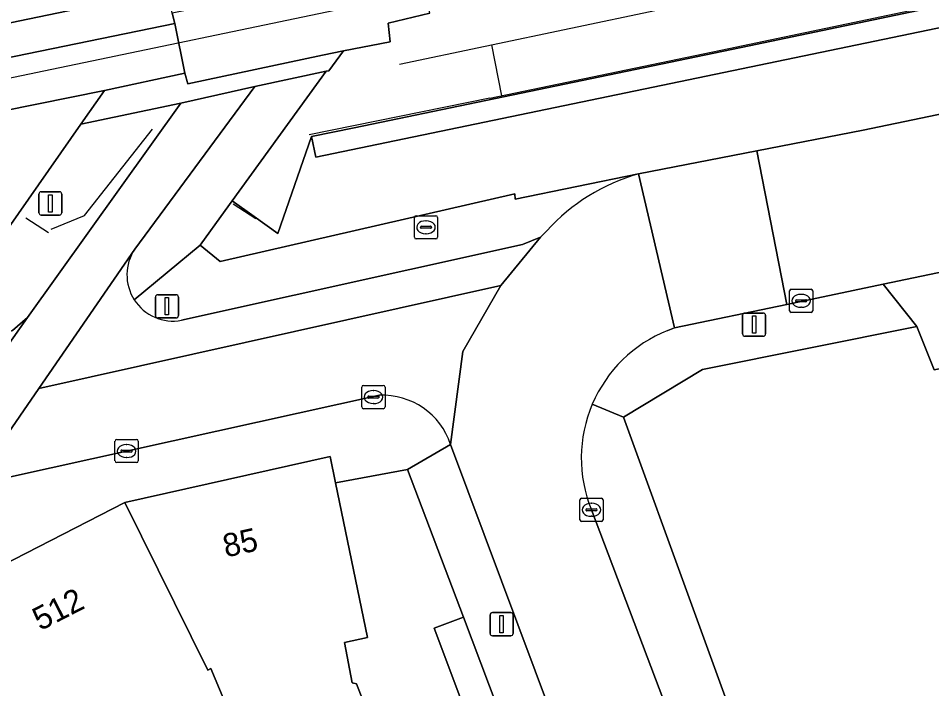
# Model space of a CAD drawing. Extents: x 162989 to 165008, y 383432 to 384338.
# Drawn here: x 163879.92 to 163919.28, y 384116.68 to 384145.59 of the extents above; entities that cross this region are included whole.
import ezdxf

# ---------------------------------------------------------------- set-up
doc = ezdxf.new("R2010")
doc.units = 0
for name, color, linetype in [('IMGEO_Erf', 7, 'Continuous'), ('IMGEO_Fietspad_open', 7, 'Continuous'), ('IMGEO_Geluidsscherm', 7, 'Continuous'), ('IMGEO_Groenvoorziening', 7, 'Continuous'), ('IMGEO_Haag', 7, 'Continuous'), ('IMGEO_Hek', 7, 'Continuous'), ('IMGEO_Kolk', 7, 'Continuous'), ('IMGEO_Lichtmast', 7, 'Continuous'), ('IMGEO_Overweg_gesloten', 7, 'Continuous'), ('IMGEO_Pand', 7, 'Continuous'), ('IMGEO_Pand_nummerreeks', 7, 'Continuous'), ('IMGEO_Rijbaan_lokaal_gesloten', 7, 'Continuous'), ('IMGEO_Rijbaan_lokaal_open', 7, 'Continuous'), ('IMGEO_Rioolput', 7, 'Continuous'), ('IMGEO_Spoor', 7, 'Continuous'), ('IMGEO_Spoorbaan_halfverhard', 7, 'Continuous'), ('IMGEO_Terreindeel_open', 7, 'Continuous'), ('IMGEO_Verkeerseiland_open', 7, 'Continuous'), ('IMGEO_Verkeersregelinstallatiepaal', 7, 'Continuous'), ('IMGEO_Voetpad_open', 7, 'Continuous')]:
    doc.layers.add(name, color=color, linetype=linetype)

msp = doc.modelspace()

# ---------------------------------------------------------------- linework, layer by layer
at = {"layer": 'IMGEO_Erf'}
msp.add_lwpolyline([(163944.693, 384087.722), (163943.187, 384090.664), (163940.668, 384096.069), (163940.042, 384097.411), (163938.387, 384100.469), (163933.086, 384111.619), (163931.815, 384114.219), (163930.51, 384116.89), (163930.356, 384117.204), (163925.265, 384126.849), (163923.141, 384131.213), (163919.387, 384130.435), (163918.639, 384132.305), (163909.406, 384130.442), (163905.997, 384128.384), (163911.891, 384112.19), (163917.32, 384097.768), (163932.033, 384058.943), (163947.096, 384019.256)], dxfattribs=at)
msp.add_lwpolyline([(163896.692, 384126.141), (163893.588, 384125.567), (163894.973, 384118.889), (163893.974, 384118.682), (163894.306, 384116.933), (163894.496, 384116.901), (163895.601, 384114.038), (163899.299, 384115.433), (163897.84, 384119.301), (163899.1, 384119.776)], close=True, dxfattribs=at)
at = {"layer": 'IMGEO_Fietspad_open'}
for points in [[(163858.262, 384092.719), (163870.014, 384113.204), (163876.697, 384123.662), (163880.797, 384129.62), (163884.94, 384135.639), (163890.116, 384142.65), (163886.926, 384141.93), (163880.31, 384132.681), (163877.756, 384129.074), (163877.678, 384128.954), (163873.799, 384123.243), (163873.714, 384123.118), (163868.266, 384114.374), (163867.368, 384112.852)], [(163900.713, 384134.073), (163902.42, 384136.156), (163901.655, 384135.828), (163886.954, 384132.566)], [(163884.94, 384135.639), (163880.797, 384129.62), (163900.713, 384134.073)], [(163877.756, 384129.074), (163880.31, 384132.681), (163879.674, 384132.131), (163878.95, 384131.916), (163877.192, 384131.789)]]:
    msp.add_lwpolyline(points, dxfattribs=at)
for centre, radius, start, end in [((163886.591, 384134.527), 1.991, 146.0445, 212.645), ((163886.595, 384134.527), 1.994, 212.5967, 280.3836)]:
    msp.add_arc(centre, radius, start, end, dxfattribs=at)
at = {"layer": 'IMGEO_Geluidsscherm'}
for points in [[(163900.238, 384142.138), (163910.539, 384144.282), (163924.865, 384147.3), (163937.597, 384149.952), (163949.238, 384152.367)], [(163900.238, 384142.138), (163892.449, 384140.554)]]:
    msp.add_lwpolyline(points, dxfattribs=at)
at = {"layer": 'IMGEO_Groenvoorziening'}
for points in [[(163976.433, 384156.982), (163892.745, 384139.603), (163892.562, 384140.484), (163891.111, 384136.301), (163890.081, 384137.041), (163889.139, 384137.718), (163888.832, 384137.295), (163887.752, 384135.808), (163888.618, 384135.1), (163901.317, 384138.016), (163901.331, 384137.791), (163906.646, 384138.881), (163911.749, 384139.874), (163916.336, 384140.767), (163989.771, 384156.06)], [(163953.785, 384153.248), (163943.293, 384151.084), (163911.419, 384144.396), (163894.397, 384140.865), (163892.562, 384140.484), (163892.745, 384139.603), (163976.433, 384156.982)]]:
    msp.add_lwpolyline(points, dxfattribs=at)
at = {"layer": 'IMGEO_Haag'}
msp.add_lwpolyline([(163953.785, 384153.248), (163943.293, 384151.084), (163911.419, 384144.396), (163894.397, 384140.865), (163892.562, 384140.484), (163892.745, 384139.603), (163976.433, 384156.982)], dxfattribs=at)
at = {"layer": 'IMGEO_Hek'}
for points in [[(163896.346, 384143.612), (163907.423, 384145.929), (163917.143, 384147.909)], [(163900.306, 384144.44), (163900.741, 384142.243)], [(163881.334, 384136.493), (163882.776, 384137.081), (163885.697, 384140.808)], [(163892.562, 384140.484), (163891.111, 384136.301), (163890.081, 384137.041), (163889.139, 384137.718)], [(163889.181, 384137.585), (163890.162, 384136.954)], [(163880.249, 384136.986), (163881.223, 384136.354)]]:
    msp.add_lwpolyline(points, dxfattribs=at)
at = {"layer": 'IMGEO_Kolk'}
for p, q in [((163913.158, 384132.98), (163913.158, 384133.832)), ((163913.233, 384133.906), (163914.085, 384133.906)), ((163914.159, 384133.832), (163914.159, 384132.98)), ((163913.417, 384133.4), (163913.417, 384133.412)), ((163913.855, 384133.363), (163913.457, 384133.363)), ((163913.46, 384133.449), (163913.858, 384133.449)), ((163913.646, 384133.686), (163913.671, 384133.686)), ((163913.901, 384133.412), (163913.901, 384133.4)), ((163913.669, 384133.126), (163913.644, 384133.126)), ((163914.085, 384132.906), (163913.233, 384132.906)), ((163894.722, 384128.831), (163894.722, 384129.683)), ((163894.797, 384129.757), (163895.649, 384129.757)), ((163895.21, 384129.537), (163895.235, 384129.537)), ((163895.723, 384129.683), (163895.723, 384128.831)), ((163894.981, 384129.251), (163894.981, 384129.263)), ((163895.419, 384129.214), (163895.021, 384129.214)), ((163895.024, 384129.3), (163895.422, 384129.3)), ((163895.233, 384128.977), (163895.208, 384128.977)), ((163895.465, 384129.263), (163895.465, 384129.251)), ((163895.649, 384128.757), (163894.797, 384128.757)), ((163884.161, 384127.43), (163885.013, 384127.43)), ((163884.086, 384126.504), (163884.086, 384127.356)), ((163884.574, 384127.21), (163884.599, 384127.21)), ((163885.087, 384127.356), (163885.087, 384126.504)), ((163884.345, 384126.924), (163884.345, 384126.936)), ((163884.783, 384126.887), (163884.385, 384126.887)), ((163884.388, 384126.973), (163884.786, 384126.973)), ((163884.597, 384126.65), (163884.572, 384126.65)), ((163884.829, 384126.936), (163884.829, 384126.924)), ((163885.013, 384126.43), (163884.161, 384126.43)), ((163904.119, 384123.971), (163904.119, 384124.823)), ((163904.194, 384124.897), (163905.046, 384124.897)), ((163904.607, 384124.677), (163904.632, 384124.677)), ((163905.12, 384124.823), (163905.12, 384123.971)), ((163904.378, 384124.391), (163904.378, 384124.403)), ((163904.816, 384124.354), (163904.418, 384124.354)), ((163904.421, 384124.44), (163904.819, 384124.44)), ((163904.862, 384124.403), (163904.862, 384124.391)), ((163905.046, 384123.897), (163904.194, 384123.897)), ((163904.63, 384124.117), (163904.605, 384124.117))]:
    msp.add_line(p, q, dxfattribs=at)
for points in [[(163913.158, 384132.98), (163913.158, 384133.832)], [(163913.233, 384133.906), (163914.085, 384133.906)], [(163914.159, 384133.832), (163914.159, 384132.98)], [(163914.085, 384132.906), (163913.233, 384132.906)], [(163894.722, 384128.831), (163894.722, 384129.683)], [(163894.797, 384129.757), (163895.649, 384129.757)], [(163895.723, 384129.683), (163895.723, 384128.831)], [(163895.649, 384128.757), (163894.797, 384128.757)], [(163884.161, 384127.43), (163885.013, 384127.43)], [(163884.086, 384126.504), (163884.086, 384127.356)], [(163885.087, 384127.356), (163885.087, 384126.504)], [(163885.013, 384126.43), (163884.161, 384126.43)], [(163904.119, 384123.971), (163904.119, 384124.823)], [(163904.194, 384124.897), (163905.046, 384124.897)], [(163905.12, 384124.823), (163905.12, 384123.971)], [(163905.046, 384123.897), (163904.194, 384123.897)]]:
    msp.add_lwpolyline(points, dxfattribs=at)
for centre, radius, start, end in [((163913.235, 384133.83), 0.0765, 91.552, 178.448), ((163913.235, 384133.83), 0.0765, 91.552, 178.448), ((163914.083, 384133.83), 0.0765, 1.552, 88.448), ((163914.083, 384133.83), 0.0765, 1.552, 88.448), ((163913.457, 384133.409), 0.0403, 85.8775, 175.7526), ((163913.454, 384133.399), 0.0366, 178.938, 274.7102), ((163913.858, 384133.406), 0.043, 264.8664, 352.4533), ((163913.862, 384133.411), 0.0386, 1.7309, 96.639), ((163913.235, 384132.982), 0.0765, 181.552, 268.448), ((163913.235, 384132.982), 0.0765, 181.552, 268.448), ((163914.083, 384132.982), 0.0765, 271.552, 358.448), ((163914.083, 384132.982), 0.0765, 271.552, 358.448), ((163894.799, 384129.681), 0.0765, 91.552, 178.448), ((163894.799, 384129.681), 0.0765, 91.552, 178.448), ((163895.647, 384129.681), 0.0765, 1.552, 88.448), ((163895.647, 384129.681), 0.0765, 1.552, 88.448), ((163895.021, 384129.26), 0.0403, 85.8775, 175.7526), ((163895.018, 384129.25), 0.0366, 178.938, 274.7102), ((163895.422, 384129.257), 0.043, 264.8664, 352.4533), ((163895.426, 384129.262), 0.0386, 1.7309, 96.639), ((163894.799, 384128.833), 0.0765, 181.552, 268.448), ((163894.799, 384128.833), 0.0765, 181.552, 268.448), ((163895.647, 384128.833), 0.0765, 271.552, 358.448), ((163895.647, 384128.833), 0.0765, 271.552, 358.448), ((163884.163, 384127.354), 0.0765, 91.552, 178.448), ((163884.163, 384127.354), 0.0765, 91.552, 178.448), ((163885.011, 384127.354), 0.0765, 1.552, 88.448), ((163885.011, 384127.354), 0.0765, 1.552, 88.448), ((163884.385, 384126.933), 0.0403, 85.8775, 175.7526), ((163884.382, 384126.923), 0.0366, 178.938, 274.7102), ((163884.786, 384126.93), 0.043, 264.8664, 352.4533), ((163884.79, 384126.935), 0.0386, 1.7309, 96.639), ((163884.163, 384126.506), 0.0765, 181.552, 268.448), ((163884.163, 384126.506), 0.0765, 181.552, 268.448), ((163885.011, 384126.506), 0.0765, 271.552, 358.448), ((163885.011, 384126.506), 0.0765, 271.552, 358.448), ((163904.196, 384124.821), 0.0765, 91.552, 178.448), ((163904.196, 384124.821), 0.0765, 91.552, 178.448), ((163905.044, 384124.821), 0.0765, 1.552, 88.448), ((163905.044, 384124.821), 0.0765, 1.552, 88.448), ((163904.418, 384124.4), 0.0403, 85.8775, 175.7526), ((163904.415, 384124.39), 0.0366, 178.938, 274.7102), ((163904.819, 384124.397), 0.043, 264.8664, 352.4533), ((163904.823, 384124.402), 0.0386, 1.7309, 96.639), ((163904.196, 384123.973), 0.0765, 181.552, 268.448), ((163904.196, 384123.973), 0.0765, 181.552, 268.448), ((163905.044, 384123.973), 0.0765, 271.552, 358.448), ((163905.044, 384123.973), 0.0765, 271.552, 358.448)]:
    msp.add_arc(centre, radius, start, end, dxfattribs=at)
for centre, major_axis, ratio, start_param, end_param in [((163913.645, 384133.406), (-0.387, 0.002), 0.722429, 4.712389, 7.853982), ((163913.67, 384133.406), (-0.39, 0.002), 0.717154, 1.570796, 4.712389), ((163895.209, 384129.257), (-0.387, 0.002), 0.722429, 4.712389, 7.853982), ((163895.234, 384129.257), (-0.39, 0.002), 0.717154, 1.570796, 4.712389), ((163884.573, 384126.93), (-0.387, 0.002), 0.722429, 4.712389, 7.853982), ((163884.598, 384126.93), (-0.39, 0.002), 0.717154, 1.570796, 4.712389), ((163904.606, 384124.397), (-0.387, 0.002), 0.722429, 4.712389, 7.853982), ((163904.631, 384124.397), (-0.39, 0.002), 0.717154, 1.570796, 4.712389)]:
    msp.add_ellipse(centre, major_axis=major_axis, ratio=ratio, start_param=start_param, end_param=end_param, dxfattribs=at)
at = {"layer": 'IMGEO_Lichtmast'}
for p, q in [((163911.136, 384131.981), (163911.136, 384132.781)), ((163911.136, 384132.781), (163911.136, 384131.981)), ((163911.236, 384132.881), (163912.026, 384132.881)), ((163912.026, 384132.881), (163911.236, 384132.881)), ((163912.126, 384132.781), (163912.126, 384131.981)), ((163912.126, 384131.981), (163912.126, 384132.781)), ((163912.026, 384131.881), (163911.236, 384131.881)), ((163911.236, 384131.881), (163912.026, 384131.881)), ((163900.35, 384119.965), (163901.14, 384119.965)), ((163901.14, 384119.965), (163900.35, 384119.965)), ((163900.25, 384119.065), (163900.25, 384119.865)), ((163900.25, 384119.865), (163900.25, 384119.065)), ((163901.24, 384119.865), (163901.24, 384119.065)), ((163901.24, 384119.065), (163901.24, 384119.865)), ((163901.14, 384118.965), (163900.35, 384118.965)), ((163900.35, 384118.965), (163901.14, 384118.965))]:
    msp.add_line(p, q, dxfattribs=at)
for points in [[(163911.556, 384132.756), (163911.706, 384132.756), (163911.706, 384132.006), (163911.556, 384132.006), (163911.556, 384132.756)], [(163900.67, 384119.84), (163900.82, 384119.84), (163900.82, 384119.09), (163900.67, 384119.09), (163900.67, 384119.84)]]:
    msp.add_lwpolyline(points, dxfattribs=at)
for centre, start, end in [((163911.236, 384132.781), 90, 180), ((163911.236, 384132.781), 90, 180), ((163912.026, 384132.781), 0, 90), ((163912.026, 384132.781), 360, 90), ((163911.236, 384131.981), 180, 270), ((163911.236, 384131.981), 180, 270), ((163912.026, 384131.981), 270, 0), ((163912.026, 384131.981), 270, 0), ((163900.35, 384119.865), 90, 180), ((163900.35, 384119.865), 90, 180), ((163901.14, 384119.865), 0, 90), ((163901.14, 384119.865), 360, 90), ((163900.35, 384119.065), 180, 270), ((163900.35, 384119.065), 180, 270), ((163901.14, 384119.065), 270, 0), ((163901.14, 384119.065), 270, 0)]:
    msp.add_arc(centre, 0.1, start, end, dxfattribs=at)
at = {"layer": 'IMGEO_Overweg_gesloten'}
for points in [[(163887.436, 384147.028), (163890.186, 384147.601), (163889.762, 384149.774), (163888.918, 384149.602), (163880.117, 384147.805), (163875.498, 384146.807), (163872.137, 384146.081), (163872.55, 384143.931), (163887.405, 384147.022)], [(163890.332, 384146.853), (163890.383, 384146.595), (163886.557, 384145.81), (163886.663, 384145.362), (163887.095, 384143.225), (163887.222, 384142.762), (163893.034, 384143.99), (163893.927, 384144.186), (163895.946, 384144.574), (163895.864, 384145.378), (163897.66, 384145.8), (163897.335, 384147.214), (163899.364, 384147.663), (163899.232, 384148.352), (163899.175, 384148.649)], [(163887.095, 384143.225), (163886.663, 384145.362), (163875.53, 384143.078), (163872.569, 384142.426), (163872.034, 384142.315), (163869.07, 384141.702), (163869.535, 384139.534), (163870.466, 384139.819), (163883.633, 384142.477)]]:
    msp.add_lwpolyline(points, close=True, dxfattribs=at)
at = {"layer": 'IMGEO_Pand'}
for points in [[(163895.601, 384114.038), (163894.496, 384116.901), (163894.306, 384116.933), (163893.974, 384118.682), (163894.973, 384118.889), (163893.588, 384125.567), (163893.354, 384126.698), (163884.516, 384124.719), (163888.09, 384117.489), (163888.221, 384117.556), (163889.151, 384115.323)], [(163901.721, 384112.825), (163899.1, 384119.776), (163897.84, 384119.301), (163899.299, 384115.433)]]:
    msp.add_lwpolyline(points, dxfattribs=at)
msp.add_lwpolyline([(163884.516, 384124.719), (163876.517, 384120.624), (163878.774, 384116.163), (163880.994, 384111.502), (163881.419, 384111.589), (163883.158, 384112.529), (163884.344, 384113.17), (163884.496, 384112.879), (163889.151, 384115.323), (163888.221, 384117.556), (163888.09, 384117.489)], close=True, dxfattribs=at)
at = {"layer": 'IMGEO_Rijbaan_lokaal_gesloten'}
for points in [[(163923.113, 384135.366), (163960.826, 384143.251), (163966.926, 384144.526), (163982.743, 384147.834), (163986.464, 384148.612), (163997.553, 384150.93), (164000, 384151.442), (164001.293, 384151.706), (164009.768, 384153.438), (164008.393, 384160.13), (164000, 384158.405), (163989.771, 384156.06), (163916.336, 384140.767), (163911.749, 384139.874), (163913.038, 384133.253), (163917.195, 384134.125)], [(163886.663, 384145.362), (163886.557, 384145.81), (163886.498, 384146.061), (163887.007, 384146.153), (163887.47, 384146.785), (163887.436, 384147.028), (163887.405, 384147.022), (163872.55, 384143.931), (163872.638, 384143.474), (163872.682, 384143.27), (163872.009, 384142.45), (163872.034, 384142.315), (163872.569, 384142.426), (163875.53, 384143.078)]]:
    msp.add_lwpolyline(points, close=True, dxfattribs=at)
msp.add_lwpolyline([(163876.691, 384132.556), (163882.616, 384141.024), (163883.633, 384142.477), (163870.466, 384139.819)], dxfattribs=at)
at = {"layer": 'IMGEO_Rijbaan_lokaal_open'}
msp.add_lwpolyline([(163911.749, 384139.874), (163906.646, 384138.881), (163908.193, 384132.237), (163913.038, 384133.253)], close=True, dxfattribs=at)
for points in [[(163907.907, 384132.131), (163908.193, 384132.237), (163906.646, 384138.881)], [(163902.699, 384136.428), (163902.42, 384136.156), (163900.713, 384134.073), (163899.073, 384131.221), (163898.552, 384127.219), (163903.65, 384113.577), (163905.658, 384108.202), (163908.244, 384101.283), (163909.453, 384098.047), (163932.403, 384037.527), (163941.155, 384014.522), (163945.705, 384016.169), (163943.363, 384022.339), (163928.089, 384062.572), (163925.404, 384069.644), (163909.585, 384111.313)], [(163900.713, 384134.073), (163880.797, 384129.62), (163876.697, 384123.662)], [(163898.552, 384127.219), (163899.073, 384131.221), (163900.713, 384134.073)], [(163879.586, 384125.813), (163895.485, 384129.337)], [(163909.585, 384111.313), (163904.617, 384124.401)]]:
    msp.add_lwpolyline(points, dxfattribs=at)
for centre, radius, start, end in [((163908.966, 384130.746), 8.459, 105.9178, 137.8028), ((163910.112, 384126.627), 5.929, 111.8274, 156.9435), ((163895.597, 384126.219), 3.12, 18.6935, 92.0504), ((163910.111, 384126.628), 5.928, 156.9518, 202.0656)]:
    msp.add_arc(centre, radius, start, end, dxfattribs=at)
at = {"layer": 'IMGEO_Rioolput'}
for p, q in [((163896.989, 384136.15), (163896.989, 384137.002)), ((163897.064, 384137.076), (163897.916, 384137.076)), ((163897.477, 384136.856), (163897.502, 384136.856)), ((163897.99, 384137.002), (163897.99, 384136.15)), ((163897.248, 384136.57), (163897.248, 384136.582)), ((163897.686, 384136.533), (163897.288, 384136.533)), ((163897.291, 384136.619), (163897.689, 384136.619)), ((163897.732, 384136.582), (163897.732, 384136.57)), ((163897.916, 384136.076), (163897.064, 384136.076)), ((163897.5, 384136.296), (163897.475, 384136.296))]:
    msp.add_line(p, q, dxfattribs=at)
for points in [[(163896.989, 384136.15), (163896.989, 384137.002)], [(163897.064, 384137.076), (163897.916, 384137.076)], [(163897.99, 384137.002), (163897.99, 384136.15)], [(163897.916, 384136.076), (163897.064, 384136.076)]]:
    msp.add_lwpolyline(points, dxfattribs=at)
for centre, radius, start, end in [((163897.066, 384137), 0.0765, 91.552, 178.448), ((163897.066, 384137), 0.0765, 91.552, 178.448), ((163897.914, 384137), 0.0765, 1.552, 88.448), ((163897.914, 384137), 0.0765, 1.552, 88.448), ((163897.288, 384136.579), 0.0403, 85.8775, 175.7526), ((163897.285, 384136.569), 0.0366, 178.938, 274.7102), ((163897.689, 384136.576), 0.043, 264.8664, 352.4533), ((163897.693, 384136.581), 0.0386, 1.7309, 96.639), ((163897.066, 384136.152), 0.0765, 181.552, 268.448), ((163897.066, 384136.152), 0.0765, 181.552, 268.448), ((163897.914, 384136.152), 0.0765, 271.552, 358.448), ((163897.914, 384136.152), 0.0765, 271.552, 358.448)]:
    msp.add_arc(centre, radius, start, end, dxfattribs=at)
for centre, major_axis, ratio, start_param, end_param in [((163897.476, 384136.576), (-0.387, 0.002), 0.722429, 4.712389, 7.853982), ((163897.501, 384136.576), (-0.39, 0.002), 0.717154, 1.570796, 4.712389)]:
    msp.add_ellipse(centre, major_axis=major_axis, ratio=ratio, start_param=start_param, end_param=end_param, dxfattribs=at)
at = {"layer": 'IMGEO_Spoor'}
msp.add_lwpolyline([(164789.572, 384332.389), (164775.58, 384329.429), (164644.744, 384302.256), (164570.629, 384286.722), (164345.336, 384239.894), (164220.116, 384213.747), (164092.662, 384187.275), (164071.527, 384182.957), (163942.979, 384156.119), (163900.983, 384147.477), (163806.025, 384127.659), (163575.669, 384079.775)], dxfattribs=at)
at = {"layer": 'IMGEO_Spoorbaan_halfverhard'}
msp.add_lwpolyline([(163897.66, 384145.8), (163895.864, 384145.378), (163895.946, 384144.574), (163893.927, 384144.186), (163893.305, 384143.315), (163893.194, 384143.302), (163889.139, 384137.718), (163890.081, 384137.041), (163891.111, 384136.301), (163892.562, 384140.484), (163894.397, 384140.865), (163911.419, 384144.396), (163943.293, 384151.084)], dxfattribs=at)
at = {"layer": 'IMGEO_Terreindeel_open'}
msp.add_lwpolyline([(163890.116, 384142.65), (163893.194, 384143.302), (163893.305, 384143.315), (163893.927, 384144.186), (163893.034, 384143.99), (163887.222, 384142.762), (163887.095, 384143.225), (163883.633, 384142.477), (163882.616, 384141.024), (163886.926, 384141.93)], close=True, dxfattribs=at)
at = {"layer": 'IMGEO_Verkeerseiland_open'}
msp.add_lwpolyline([(163877.192, 384131.789), (163878.95, 384131.916), (163879.674, 384132.131), (163880.31, 384132.681), (163886.926, 384141.93), (163882.616, 384141.024), (163876.691, 384132.556), (163876.647, 384132.131)], dxfattribs=at)
at = {"layer": 'IMGEO_Verkeersregelinstallatiepaal'}
for p, q in [((163880.904, 384138.105), (163881.694, 384138.105)), ((163881.694, 384138.105), (163880.904, 384138.105)), ((163880.804, 384137.205), (163880.804, 384138.005)), ((163880.804, 384138.005), (163880.804, 384137.205)), ((163881.794, 384138.005), (163881.794, 384137.205)), ((163881.794, 384137.205), (163881.794, 384138.005)), ((163881.694, 384137.105), (163880.904, 384137.105)), ((163880.904, 384137.105), (163881.694, 384137.105)), ((163885.828, 384132.77), (163885.828, 384133.57)), ((163885.828, 384133.57), (163885.828, 384132.77)), ((163885.928, 384133.67), (163886.718, 384133.67)), ((163886.718, 384133.67), (163885.928, 384133.67)), ((163886.818, 384133.57), (163886.818, 384132.77)), ((163886.818, 384132.77), (163886.818, 384133.57)), ((163886.718, 384132.67), (163885.928, 384132.67)), ((163885.928, 384132.67), (163886.718, 384132.67))]:
    msp.add_line(p, q, dxfattribs=at)
for points in [[(163881.224, 384137.98), (163881.374, 384137.98), (163881.374, 384137.23), (163881.224, 384137.23), (163881.224, 384137.98)], [(163886.248, 384133.545), (163886.398, 384133.545), (163886.398, 384132.795), (163886.248, 384132.795), (163886.248, 384133.545)]]:
    msp.add_lwpolyline(points, dxfattribs=at)
for centre, start, end in [((163880.904, 384138.005), 90, 180), ((163880.904, 384138.005), 90, 180), ((163881.694, 384138.005), 0, 90), ((163881.694, 384138.005), 360, 90), ((163880.904, 384137.205), 180, 270), ((163880.904, 384137.205), 180, 270), ((163881.694, 384137.205), 270, 0), ((163881.694, 384137.205), 270, 0), ((163885.928, 384133.57), 90, 180), ((163885.928, 384133.57), 90, 180), ((163886.718, 384133.57), 0, 90), ((163886.718, 384133.57), 360, 90), ((163885.928, 384132.77), 180, 270), ((163885.928, 384132.77), 180, 270), ((163886.718, 384132.77), 270, 0), ((163886.718, 384132.77), 270, 0)]:
    msp.add_arc(centre, 0.1, start, end, dxfattribs=at)
at = {"layer": 'IMGEO_Voetpad_open'}
for points in [[(163884.915, 384133.453), (163887.752, 384135.808), (163888.832, 384137.295), (163889.139, 384137.718), (163893.194, 384143.302)], [(163893.194, 384143.302), (163890.116, 384142.65), (163884.94, 384135.639)], [(163906.646, 384138.881), (163901.331, 384137.791), (163901.317, 384138.016)], [(163901.317, 384138.016), (163888.618, 384135.1), (163887.752, 384135.808), (163884.915, 384133.453)], [(163886.954, 384132.566), (163901.655, 384135.828), (163902.42, 384136.156), (163902.699, 384136.428)], [(163918.639, 384132.305), (163917.195, 384134.125), (163913.038, 384133.253), (163908.193, 384132.237), (163907.907, 384132.131)], [(163904.656, 384128.949), (163905.997, 384128.384), (163909.406, 384130.442), (163918.639, 384132.305)], [(163895.485, 384129.337), (163879.586, 384125.813), (163876.517, 384120.624), (163884.516, 384124.719), (163893.354, 384126.698), (163893.588, 384125.567), (163896.692, 384126.141), (163898.552, 384127.219)], [(163905.997, 384128.384), (163904.656, 384128.949)], [(163904.617, 384124.401), (163909.585, 384111.313), (163910.739, 384111.752), (163911.891, 384112.19), (163905.997, 384128.384)]]:
    msp.add_lwpolyline(points, dxfattribs=at)
for points in [[(163923.113, 384135.366), (163917.195, 384134.125), (163918.639, 384132.305), (163919.387, 384130.435), (163923.141, 384131.213), (163923.697, 384131.328)], [(163898.552, 384127.219), (163896.692, 384126.141), (163899.1, 384119.776), (163901.721, 384112.825), (163903.65, 384113.577)]]:
    msp.add_lwpolyline(points, close=True, dxfattribs=at)
for centre, radius, start, end in [((163908.966, 384130.746), 8.459, 105.9178, 137.8028), ((163886.591, 384134.527), 1.991, 146.0445, 212.645), ((163886.595, 384134.527), 1.994, 212.5967, 280.3836), ((163910.112, 384126.627), 5.929, 111.8274, 156.9435), ((163895.597, 384126.219), 3.12, 18.6935, 92.0504), ((163910.111, 384126.628), 5.928, 156.9518, 202.0656)]:
    msp.add_arc(centre, radius, start, end, dxfattribs=at)

# ---------------------------------------------------------------- texts
at = {"layer": 'IMGEO_Pand_nummerreeks'}
for s, rotation, p in [('85', 12.542, (163888.863, 384122.338)), ('512', 27.1124, (163880.863, 384119.164))]:
    msp.add_text(s, height=1, rotation=rotation, dxfattribs=at).set_placement(p)

doc.saveas('drawing.dxf')
